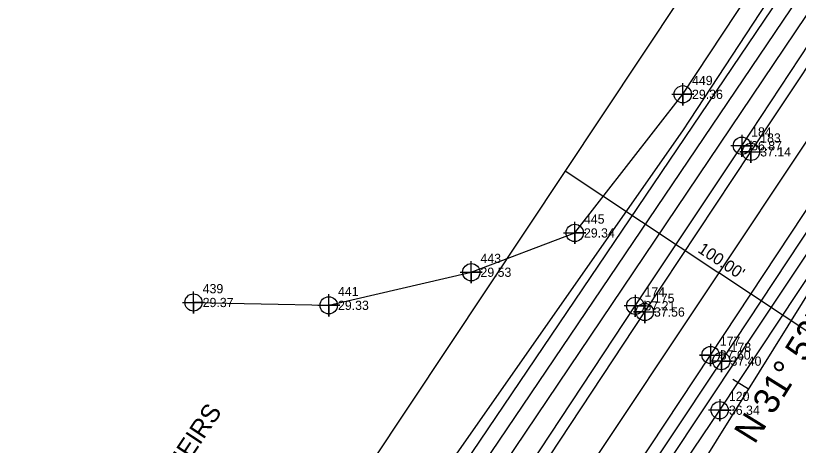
# Model space of a CAD drawing. Extents: x 2603627 to 2605187, y 896619 to 899063.
# Drawn here: x 2604004.7 to 2604216.9, y 897589.3 to 897705.9 of the extents above; entities that cross this region are included whole.
import ezdxf

# ---------------------------------------------------------------- set-up
doc = ezdxf.new("R2010")
doc.units = 0
for name, color, linetype in [('Exist Horizontal Alignment', 7, 'Continuous'), ('Exist Horizontal Baseline Alignment', 7, 'Continuous'), ('Exist Horizontal Baseline Alignment Direction Label', 7, 'Continuous'), ('Exist Horizontal Baseline Alignment Tick small', 7, 'Continuous'), ('Exist Hydro Stream or Body of Water', 7, 'Continuous'), ('Exist Hydro Stream or Body of Water Cogo Elevation', 7, 'Continuous'), ('Exist Hydro Stream or Body of Water Cogo Number', 7, 'Continuous'), ('Exist Hydro Stream or Body of Water Cogo Point CELL', 7, 'Continuous'), ('Exist Property Owner Text', 7, 'Continuous'), ('Exist Right of Way Line', 7, 'Continuous'), ('Exist Right of Way Width CELL', 7, 'Continuous'), ('Exist Roads EOP', 7, 'Continuous'), ('Exist Roads EOP Cogo Elevation', 7, 'Continuous'), ('Exist Roads EOP Cogo Number', 7, 'Continuous'), ('Exist Roads EOP Cogo Point CELL', 7, 'Continuous'), ('Exist Roads EOT', 7, 'Continuous'), ('Exist Roads EOT Cogo Elevation', 7, 'Continuous'), ('Exist Roads EOT Cogo Number', 7, 'Continuous'), ('Exist Roads EOT Cogo Point CELL', 7, 'Continuous'), ('Exist Utilities Telephone UG Cable SUE LOS C', 7, 'Continuous'), ('Exist Utilities Telephone UG FO SUE LOS C', 7, 'Continuous'), ('Exist Utilities Water UG Line SUE LOS B', 7, 'Continuous'), ('Exist Utilities Water UG Line SUE LOS B Cogo Elevation', 7, 'Continuous'), ('Exist Utilities Water UG Line SUE LOS B Cogo Number', 7, 'Continuous'), ('Exist Utilities Water UG Line SUE LOS B Cogo Point CELL', 7, 'Continuous'), ('Exist Vegetation Woods Line', 7, 'Continuous')]:
    doc.layers.add(name, color=color, linetype=linetype)

# ---------------------------------------------------------------- blocks, each defined once
blk = doc.blocks.new('EXIST UTILITIES WATER UG LINE SUE LOS B COGO POINT')
at = {"layer": 'Exist Utilities Water UG Line SUE LOS B Cogo Point CELL'}
blk.add_lwpolyline([(0, 0.06), (0, -0.06), (0, 0), (0.06, 0), (-0.06, 0)], dxfattribs=at)
blk.add_circle((0, 0), 0.0469, dxfattribs=at)
blk = doc.blocks.new('EXIST ROADS EOP COGO POINT')
at = {"layer": 'Exist Roads EOP Cogo Point CELL'}
blk.add_lwpolyline([(0, 0.06), (0, -0.06), (0, 0), (0.06, 0), (-0.06, 0)], dxfattribs=at)
blk.add_circle((0, 0), 0.0469, dxfattribs=at)
blk = doc.blocks.new('EXIST ROADS EOT COGO POINT')
at = {"layer": 'Exist Roads EOT Cogo Point CELL'}
blk.add_lwpolyline([(0, 0.06), (0, -0.06), (0, 0), (-0.06, 0), (0.06, 0)], dxfattribs=at)
blk.add_circle((0, 0), 0.0469, dxfattribs=at)
blk = doc.blocks.new('EXIST HYDRO STREAM OR BODY OF WATER COGO POINT')
at = {"layer": 'Exist Hydro Stream or Body of Water Cogo Point CELL'}
blk.add_lwpolyline([(-0.06, 0), (0.06, 0), (0, 0), (0, -0.06), (0, 0.06)], dxfattribs=at)
blk.add_circle((0, 0), 0.0469, dxfattribs=at)

msp = doc.modelspace()

# ---------------------------------------------------------------- linework, layer by layer
at = {"layer": 'Exist Horizontal Alignment'}
msp.add_line((2604046.33, 897411.6), (2604501.12, 898096.36), dxfattribs=at)
at = {"layer": 'Exist Horizontal Baseline Alignment'}
msp.add_line((2604070.2, 897390.44), (2604301.74, 897762.53), dxfattribs=at)
at = {"layer": 'Exist Horizontal Baseline Alignment Tick small'}
msp.add_line((2604203.42, 897604.53), (2604199.18, 897607.17), dxfattribs=at)
at = {"layer": 'Exist Hydro Stream or Body of Water'}
msp.add_lwpolyline([(2604052.91, 897628.09), (2604089.6, 897627.32), (2604128.24, 897636.3), (2604156.3, 897646.97), (2604185.61, 897684.58), (2604210.99, 897723.15), (2604241.46, 897770.09), (2604275.04, 897824.38), (2604301.6, 897863.35), (2604336.85, 897914.58), (2604340.35, 897931.78), (2604335.4, 897942.33), (2604319.35, 897951.81), (2604291.45, 897956.13), (2604263.34, 897978.85)], dxfattribs=at)
at = {"layer": 'Exist Right of Way Line'}
msp.add_line((2604004.68, 897439.26), (2604459.47, 898124.02), dxfattribs=at)
at = {"layer": 'Exist Right of Way Width CELL'}
for p in [(2604153.75, 897663.77), (2604237.05, 897608.45)]:
    msp.add_line(p, (2604195.1, 897636.31), dxfattribs=at)
at = {"layer": 'Exist Roads EOP'}
for points in [[(2604034.94, 897419.16), (2604054.97, 897449.51), (2604085.58, 897495.18), (2604114.88, 897539.87), (2604143.93, 897583.57), (2604172.72, 897627.19), (2604201.64, 897670.62), (2604230.5, 897714.45), (2604261.1, 897760.21), (2604291.23, 897805.76), (2604320.82, 897850.24), (2604350.34, 897894.81), (2604379.01, 897938.02), (2604408.4, 897982.56), (2604438.29, 898027.28), (2604468.22, 898072.28), (2604496.92, 898115.7)], [(2604057.72, 897404.05), (2604078.22, 897434.83), (2604108.36, 897480.05), (2604137.93, 897524.86), (2604167.35, 897568.96), (2604196.06, 897612.17), (2604224.86, 897655.68), (2604253.51, 897698.95), (2604283.96, 897744.64), (2604314.74, 897791.03), (2604343.97, 897835.34), (2604373.31, 897879.6), (2604402.1, 897923.18), (2604431.64, 897967.59), (2604461.24, 898012.02), (2604491.05, 898056.88), (2604519.7, 898100.47)]]:
    msp.add_lwpolyline(points, dxfattribs=at)
at = {"layer": 'Exist Roads EOT'}
for points in [[(2604037.37, 897417.54), (2604057.46, 897447.93), (2604087.91, 897493.66), (2604117.35, 897538.28), (2604146.54, 897581.98), (2604175.28, 897625.51), (2604204.1, 897668.97), (2604233.05, 897712.63), (2604263.81, 897758.51), (2604293.89, 897804.07), (2604323.3, 897848.54), (2604352.86, 897893.08), (2604381.65, 897936.11), (2604411.04, 897980.65), (2604440.78, 898025.82), (2604470.61, 898070.74), (2604499.36, 898114.11)], [(2604055.13, 897405.77), (2604075.39, 897436.3), (2604105.72, 897481.84), (2604135.41, 897526.58), (2604164.51, 897570.47), (2604193.14, 897613.84), (2604222.02, 897657.58), (2604250.73, 897700.63), (2604281.08, 897746.07), (2604311.9, 897792.56), (2604341.37, 897836.94), (2604370.82, 897881.24), (2604399.64, 897924.71), (2604429.03, 897968.88), (2604458.85, 898013.95), (2604488.44, 898058.33), (2604517.14, 898101.52)]]:
    msp.add_lwpolyline(points, dxfattribs=at)
at = {"layer": 'Exist Utilities Telephone UG Cable SUE LOS C'}
for p, q in [((2604201.56, 897614.6), (2604426.24, 897952.72)), ((2604109.59, 897543.22), (2604364.02, 897921.59)), ((2604060.46, 897402.24), (2604201.56, 897614.6))]:
    msp.add_line(p, q, dxfattribs=at)
at = {"layer": 'Exist Utilities Telephone UG FO SUE LOS C'}
for p, q in [((2604020.98, 897428.41), (2604461.82, 898080.46)), ((2604024.53, 897426.06), (2604465.37, 898078.1))]:
    msp.add_line(p, q, dxfattribs=at)
at = {"layer": 'Exist Utilities Water UG Line SUE LOS B'}
msp.add_lwpolyline([(2604076.5, 897391.6), (2604089.19, 897412.44), (2604108.02, 897444.81), (2604130.46, 897486.17), (2604138.61, 897502.5), (2604141.74, 897510.42), (2604157.29, 897542.11), (2604195.61, 897598.86), (2604232.99, 897655.2), (2604269.72, 897709.19), (2604303.43, 897758.71), (2604343.24, 897819.02), (2604371.6, 897861.28), (2604402.52, 897906.63), (2604434.42, 897955.25), (2604460.63, 897996.69), (2604477.79, 898022.59), (2604502.25, 898059.64), (2604529.4, 898098.89), (2604530.47, 898100.43), (2604537.02, 898109.88), (2604550.55, 898129.28)], dxfattribs=at)
at = {"layer": 'Exist Vegetation Woods Line'}
for points in [[(2604476.15, 898117.83), (2604185.5, 897674.67)], [(2604185.5, 897674.67), (2604015.65, 897431.94)]]:
    msp.add_lwpolyline(points, dxfattribs=at)

# ---------------------------------------------------------------- block references
at = {"layer": 'Exist Hydro Stream or Body of Water Cogo Point CELL', "xscale": 50, "yscale": 50}
for p in [(2604185.61, 897684.58), (2604156.3, 897646.97), (2604128.24, 897636.3), (2604052.91, 897628.09), (2604089.6, 897627.32)]:
    msp.add_blockref('EXIST HYDRO STREAM OR BODY OF WATER COGO POINT', p, dxfattribs=at)
at = {"layer": 'Exist Roads EOP Cogo Point CELL', "xscale": 50, "yscale": 50}
for p in [(2604201.64, 897670.62), (2604172.72, 897627.19), (2604196.06, 897612.17)]:
    msp.add_blockref('EXIST ROADS EOP COGO POINT', p, dxfattribs=at)
at = {"layer": 'Exist Roads EOT Cogo Point CELL', "xscale": 50, "yscale": 50}
for p in [(2604204.1, 897668.97), (2604175.28, 897625.51), (2604193.14, 897613.84)]:
    msp.add_blockref('EXIST ROADS EOT COGO POINT', p, dxfattribs=at)
at = {"layer": 'Exist Utilities Water UG Line SUE LOS B Cogo Point CELL', "xscale": 50, "yscale": 50}
msp.add_blockref('EXIST UTILITIES WATER UG LINE SUE LOS B COGO POINT', (2604195.61, 897598.86), dxfattribs=at)

# ---------------------------------------------------------------- texts
at = {"layer": 'Exist Horizontal Baseline Alignment Direction Label'}
msp.add_text('N 31%%d 53\' 35.6" E', height=7, rotation=58.1068, dxfattribs=at).set_placement((2604205.07, 897589.39))
at = {"layer": 'Exist Hydro Stream or Body of Water Cogo Elevation'}
for s, p in [('29.36', (2604188.11, 897683.33)), ('29.34', (2604158.8, 897645.72)), ('29.53', (2604130.74, 897635.05)), ('29.37', (2604055.41, 897626.84)), ('29.33', (2604092.1, 897626.07))]:
    msp.add_text(s, height=2.5, dxfattribs=at).set_placement(p)
at = {"layer": 'Exist Hydro Stream or Body of Water Cogo Number'}
for s, p in [('449', (2604188.11, 897687.08)), ('445', (2604158.8, 897649.47)), ('443', (2604130.74, 897638.8)), ('439', (2604055.41, 897630.59)), ('441', (2604092.1, 897629.82))]:
    msp.add_text(s, height=2.5, dxfattribs=at).set_placement(p)
at = {"layer": 'Exist Property Owner Text'}
msp.add_text('W.R. HARMON HEIRS', height=5, rotation=56.4133, dxfattribs=at).set_placement((2604022.76, 897541.24))
at = {"layer": 'Exist Right of Way Width CELL'}
msp.add_text("100.00'", height=3.2, rotation=326.4094, dxfattribs=at).set_placement((2604189.43, 897641.9))
at = {"layer": 'Exist Roads EOP Cogo Elevation'}
for s, p in [('36.87', (2604204.14, 897669.37)), ('37.21', (2604175.22, 897625.94)), ('37.40', (2604198.56, 897610.92))]:
    msp.add_text(s, height=2.5, dxfattribs=at).set_placement(p)
at = {"layer": 'Exist Roads EOP Cogo Number'}
for s, p in [('184', (2604204.14, 897673.12)), ('174', (2604175.22, 897629.69)), ('178', (2604198.56, 897614.67))]:
    msp.add_text(s, height=2.5, dxfattribs=at).set_placement(p)
at = {"layer": 'Exist Roads EOT Cogo Elevation'}
for s, p in [('37.14', (2604206.6, 897667.72)), ('37.56', (2604177.78, 897624.26)), ('37.60', (2604195.64, 897612.59))]:
    msp.add_text(s, height=2.5, dxfattribs=at).set_placement(p)
at = {"layer": 'Exist Roads EOT Cogo Number'}
for s, p in [('183', (2604206.6, 897671.47)), ('175', (2604177.78, 897628.01)), ('177', (2604195.64, 897616.34))]:
    msp.add_text(s, height=2.5, dxfattribs=at).set_placement(p)
at = {"layer": 'Exist Utilities Water UG Line SUE LOS B Cogo Elevation'}
msp.add_text('36.34', height=2.5, dxfattribs=at).set_placement((2604198.11, 897597.61))
at = {"layer": 'Exist Utilities Water UG Line SUE LOS B Cogo Number'}
msp.add_text('120', height=2.5, dxfattribs=at).set_placement((2604198.11, 897601.36))

doc.saveas('drawing.dxf')
